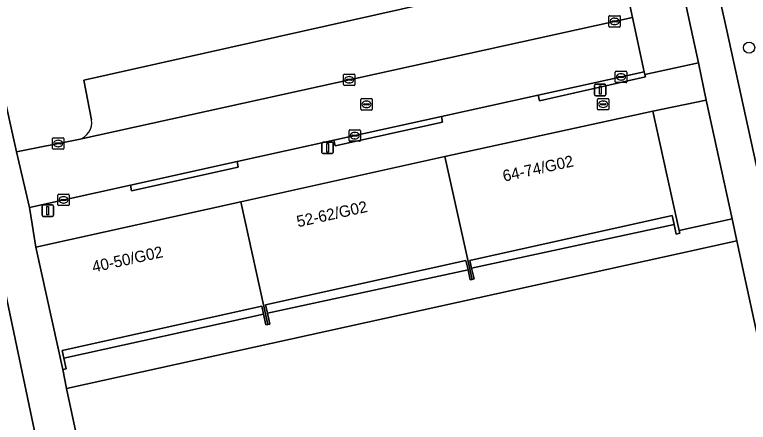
# Model space of a CAD drawing. Extents: x 160030 to 160839, y 385325 to 386450.
# Drawn here: x 160686.5 to 160750.9, y 385671.3 to 385707.1 of the extents above; entities that cross this region are included whole.
import ezdxf

# ---------------------------------------------------------------- set-up
doc = ezdxf.new("R2010")
doc.units = 0
for name, color, linetype in [('IMGEO_Berm_groen', 7, 'Continuous'), ('IMGEO_Boom', 7, 'Continuous'), ('IMGEO_Brandkraan', 7, 'Continuous'), ('IMGEO_Groenvoorziening', 7, 'Continuous'), ('IMGEO_Kolk', 7, 'Continuous'), ('IMGEO_Lichtmast', 7, 'Continuous'), ('IMGEO_Pand', 7, 'Continuous'), ('IMGEO_Pand_nummerreeks', 7, 'Continuous'), ('IMGEO_Parkeervlak_open', 7, 'Continuous'), ('IMGEO_Rijbaan_lokaal_open', 7, 'Continuous'), ('IMGEO_Rioolput', 7, 'Continuous'), ('IMGEO_Voetpad_open', 7, 'Continuous')]:
    doc.layers.add(name, color=color, linetype=linetype)

msp = doc.modelspace()

# ---------------------------------------------------------------- linework, layer by layer
at = {"layer": 'IMGEO_Berm_groen'}
msp.add_lwpolyline([(160752.149, 385706.509), (160750.95, 385712.317), (160750.418, 385714.749), (160747.106, 385714.042), (160747.585, 385711.838), (160748.912, 385705.94), (160756.742, 385670.124), (160764.406, 385634.512), (160767.671, 385635.207)], close=True, dxfattribs=at)
at = {"layer": 'IMGEO_Boom'}
msp.add_circle((160750.925, 385704.162), 0.489, dxfattribs=at)
at = {"layer": 'IMGEO_Brandkraan'}
for p, q in [((160737.616, 385698.769), (160737.616, 385699.621)), ((160737.691, 385699.695), (160738.543, 385699.695)), ((160738.104, 385699.475), (160738.129, 385699.475)), ((160738.617, 385699.621), (160738.617, 385698.769)), ((160737.875, 385699.189), (160737.875, 385699.201)), ((160738.313, 385699.152), (160737.915, 385699.152)), ((160737.918, 385699.238), (160738.316, 385699.238)), ((160738.127, 385698.915), (160738.102, 385698.915)), ((160738.359, 385699.201), (160738.359, 385699.189)), ((160738.543, 385698.695), (160737.691, 385698.695))]:
    msp.add_line(p, q, dxfattribs=at)
for points in [[(160737.616, 385698.769), (160737.616, 385699.621)], [(160737.691, 385699.695), (160738.543, 385699.695)], [(160738.617, 385699.621), (160738.617, 385698.769)], [(160738.543, 385698.695), (160737.691, 385698.695)]]:
    msp.add_lwpolyline(points, dxfattribs=at)
for centre, radius, start, end in [((160737.693, 385699.619), 0.0765, 91.55205, 178.44795), ((160737.693, 385699.619), 0.0765, 91.55205, 178.44795), ((160738.541, 385699.619), 0.0765, 1.55205, 88.44795), ((160738.541, 385699.619), 0.0765, 1.55205, 88.44795), ((160737.915, 385699.198), 0.0403, 85.87752, 175.75265), ((160737.912, 385699.188), 0.0366, 178.93798, 274.71019), ((160738.316, 385699.195), 0.043, 264.86636, 352.45326), ((160738.32, 385699.2), 0.0386, 1.73085, 96.63898), ((160737.693, 385698.771), 0.0765, 181.55205, 268.44795), ((160737.693, 385698.771), 0.0765, 181.55205, 268.44795), ((160738.541, 385698.771), 0.0765, 271.55205, 358.44795), ((160738.541, 385698.771), 0.0765, 271.55205, 358.44795)]:
    msp.add_arc(centre, radius, start, end, dxfattribs=at)
for centre, major_axis, ratio, start_param, end_param in [((160738.103, 385699.195), (-0.387, 0.002), 0.722429, 4.712389, 7.853982), ((160738.128, 385699.195), (-0.39, 0.002), 0.717154, 1.570796, 4.712389)]:
    msp.add_ellipse(centre, major_axis=major_axis, ratio=ratio, start_param=start_param, end_param=end_param, dxfattribs=at)
at = {"layer": 'IMGEO_Groenvoorziening'}
for points in [[(160692.533, 385701.29), (160739.614, 385711.868), (160740.697, 385706.808), (160741.718, 385702.039), (160741.772, 385701.797), (160746.478, 385702.821), (160741.383, 385726.239), (160736.6, 385725.195), (160682.511, 385713.385), (160686.606, 385695.006), (160692.066, 385696.105)], [(160693.191, 385697.833), (160692.533, 385701.29)], [(160704.845, 385661.028), (160724.924, 385665.504), (160748.512, 385670.542), (160749.509, 385665.757), (160750.548, 385660.927), (160750.648, 385660.947), (160750.687, 385660.776), (160755.372, 385661.736), (160750.486, 385684.225), (160749.841, 385687.196), (160745.072, 385686.16), (160691.006, 385674.252), (160695.339, 385654.015), (160697.696, 385654.461), (160698.29, 385654.583), (160703.979, 385655.723)]]:
    msp.add_lwpolyline(points, dxfattribs=at)
msp.add_lwpolyline([(160747.158, 385699.556), (160742.472, 385698.58), (160743.709, 385692.988), (160744.787, 385688.115), (160749.423, 385689.121)], close=True, dxfattribs=at)
msp.add_arc((160691.732, 385697.553), 1.486, 282.99435, 10.87404, dxfattribs=at)
at = {"layer": 'IMGEO_Kolk'}
for p, q in [((160738.618, 385706.036), (160738.618, 385706.888)), ((160738.693, 385706.962), (160739.545, 385706.962)), ((160739.106, 385706.742), (160739.131, 385706.742)), ((160739.619, 385706.888), (160739.619, 385706.036)), ((160739.545, 385705.962), (160738.693, 385705.962)), ((160738.877, 385706.456), (160738.877, 385706.468)), ((160739.315, 385706.419), (160738.917, 385706.419)), ((160738.92, 385706.505), (160739.318, 385706.505)), ((160739.129, 385706.182), (160739.104, 385706.182)), ((160739.361, 385706.468), (160739.361, 385706.456)), ((160739.253, 385702.091), (160740.105, 385702.091)), ((160715.325, 385700.91), (160715.325, 385701.762)), ((160715.4, 385701.836), (160716.252, 385701.836)), ((160715.813, 385701.616), (160715.838, 385701.616)), ((160716.326, 385701.762), (160716.326, 385700.91)), ((160739.178, 385701.165), (160739.178, 385702.017)), ((160739.437, 385701.585), (160739.437, 385701.597)), ((160739.875, 385701.548), (160739.477, 385701.548)), ((160739.48, 385701.634), (160739.878, 385701.634)), ((160739.666, 385701.871), (160739.691, 385701.871)), ((160739.921, 385701.597), (160739.921, 385701.585)), ((160740.179, 385702.017), (160740.179, 385701.165)), ((160716.252, 385700.836), (160715.4, 385700.836)), ((160715.584, 385701.33), (160715.584, 385701.342)), ((160716.022, 385701.293), (160715.624, 385701.293)), ((160715.627, 385701.379), (160716.025, 385701.379)), ((160715.836, 385701.056), (160715.811, 385701.056)), ((160716.068, 385701.342), (160716.068, 385701.33)), ((160740.105, 385701.091), (160739.253, 385701.091)), ((160739.689, 385701.311), (160739.664, 385701.311)), ((160715.883, 385696.938), (160716.735, 385696.938)), ((160689.857, 385696.247), (160690.709, 385696.247)), ((160715.808, 385696.012), (160715.808, 385696.864)), ((160716.067, 385696.432), (160716.067, 385696.444)), ((160716.505, 385696.395), (160716.107, 385696.395)), ((160716.11, 385696.481), (160716.508, 385696.481)), ((160716.296, 385696.718), (160716.321, 385696.718)), ((160716.551, 385696.444), (160716.551, 385696.432)), ((160716.809, 385696.864), (160716.809, 385696.012)), ((160689.782, 385695.321), (160689.782, 385696.173)), ((160690.041, 385695.741), (160690.041, 385695.753)), ((160690.479, 385695.704), (160690.081, 385695.704)), ((160690.084, 385695.79), (160690.482, 385695.79)), ((160690.27, 385696.027), (160690.295, 385696.027)), ((160690.525, 385695.753), (160690.525, 385695.741)), ((160690.783, 385696.173), (160690.783, 385695.321)), ((160716.735, 385695.938), (160715.883, 385695.938)), ((160716.319, 385696.158), (160716.294, 385696.158)), ((160690.709, 385695.247), (160689.857, 385695.247)), ((160690.293, 385695.467), (160690.268, 385695.467)), ((160690.249, 385690.373), (160690.249, 385691.225)), ((160690.324, 385691.299), (160691.176, 385691.299)), ((160691.25, 385691.225), (160691.25, 385690.373)), ((160690.508, 385690.793), (160690.508, 385690.805)), ((160690.946, 385690.756), (160690.548, 385690.756)), ((160690.551, 385690.842), (160690.949, 385690.842)), ((160690.76, 385690.519), (160690.735, 385690.519)), ((160690.737, 385691.079), (160690.762, 385691.079)), ((160690.992, 385690.805), (160690.992, 385690.793)), ((160691.176, 385690.299), (160690.324, 385690.299))]:
    msp.add_line(p, q, dxfattribs=at)
for points in [[(160738.618, 385706.036), (160738.618, 385706.888)], [(160738.693, 385706.962), (160739.545, 385706.962)], [(160739.619, 385706.888), (160739.619, 385706.036)], [(160739.545, 385705.962), (160738.693, 385705.962)], [(160739.253, 385702.091), (160740.105, 385702.091)], [(160715.325, 385700.91), (160715.325, 385701.762)], [(160715.4, 385701.836), (160716.252, 385701.836)], [(160716.326, 385701.762), (160716.326, 385700.91)], [(160739.178, 385701.165), (160739.178, 385702.017)], [(160740.179, 385702.017), (160740.179, 385701.165)], [(160716.252, 385700.836), (160715.4, 385700.836)], [(160740.105, 385701.091), (160739.253, 385701.091)], [(160715.883, 385696.938), (160716.735, 385696.938)], [(160689.857, 385696.247), (160690.709, 385696.247)], [(160715.808, 385696.012), (160715.808, 385696.864)], [(160716.809, 385696.864), (160716.809, 385696.012)], [(160689.782, 385695.321), (160689.782, 385696.173)], [(160690.783, 385696.173), (160690.783, 385695.321)], [(160716.735, 385695.938), (160715.883, 385695.938)], [(160690.709, 385695.247), (160689.857, 385695.247)], [(160690.249, 385690.373), (160690.249, 385691.225)], [(160690.324, 385691.299), (160691.176, 385691.299)], [(160691.25, 385691.225), (160691.25, 385690.373)], [(160691.176, 385690.299), (160690.324, 385690.299)]]:
    msp.add_lwpolyline(points, dxfattribs=at)
for centre, radius, start, end in [((160738.695, 385706.886), 0.0765, 91.55205, 178.44795), ((160738.695, 385706.886), 0.0765, 91.55205, 178.44795), ((160739.543, 385706.886), 0.0765, 1.55205, 88.44795), ((160739.543, 385706.886), 0.0765, 1.55205, 88.44795), ((160738.695, 385706.038), 0.0765, 181.55205, 268.44795), ((160738.695, 385706.038), 0.0765, 181.55205, 268.44795), ((160738.917, 385706.465), 0.0403, 85.87752, 175.75265), ((160738.914, 385706.455), 0.0366, 178.93798, 274.71019), ((160739.318, 385706.462), 0.043, 264.86636, 352.45326), ((160739.322, 385706.467), 0.0386, 1.73085, 96.63898), ((160739.543, 385706.038), 0.0765, 271.55205, 358.44795), ((160739.543, 385706.038), 0.0765, 271.55205, 358.44795), ((160739.255, 385702.015), 0.0765, 91.55205, 178.44795), ((160739.255, 385702.015), 0.0765, 91.55205, 178.44795), ((160740.103, 385702.015), 0.0765, 1.55205, 88.44795), ((160740.103, 385702.015), 0.0765, 1.55205, 88.44795), ((160715.402, 385701.76), 0.0765, 91.55205, 178.44795), ((160715.402, 385701.76), 0.0765, 91.55205, 178.44795), ((160716.25, 385701.76), 0.0765, 1.55205, 88.44795), ((160716.25, 385701.76), 0.0765, 1.55205, 88.44795), ((160739.477, 385701.594), 0.0403, 85.87752, 175.75265), ((160739.474, 385701.584), 0.0366, 178.93798, 274.71019), ((160739.878, 385701.591), 0.043, 264.86636, 352.45326), ((160739.882, 385701.596), 0.0386, 1.73085, 96.63898), ((160715.402, 385700.912), 0.0765, 181.55205, 268.44795), ((160715.402, 385700.912), 0.0765, 181.55205, 268.44795), ((160715.624, 385701.339), 0.0403, 85.87752, 175.75265), ((160715.621, 385701.329), 0.0366, 178.93798, 274.71019), ((160716.025, 385701.336), 0.043, 264.86636, 352.45326), ((160716.029, 385701.341), 0.0386, 1.73085, 96.63898), ((160716.25, 385700.912), 0.0765, 271.55205, 358.44795), ((160716.25, 385700.912), 0.0765, 271.55205, 358.44795), ((160739.255, 385701.167), 0.0765, 181.55205, 268.44795), ((160739.255, 385701.167), 0.0765, 181.55205, 268.44795), ((160740.103, 385701.167), 0.0765, 271.55205, 358.44795), ((160740.103, 385701.167), 0.0765, 271.55205, 358.44795), ((160715.885, 385696.862), 0.0765, 91.55205, 178.44795), ((160715.885, 385696.862), 0.0765, 91.55205, 178.44795), ((160716.733, 385696.862), 0.0765, 1.55205, 88.44795), ((160716.733, 385696.862), 0.0765, 1.55205, 88.44795), ((160689.859, 385696.171), 0.0765, 91.55205, 178.44795), ((160689.859, 385696.171), 0.0765, 91.55205, 178.44795), ((160690.707, 385696.171), 0.0765, 1.55205, 88.44795), ((160690.707, 385696.171), 0.0765, 1.55205, 88.44795), ((160716.107, 385696.441), 0.0403, 85.87752, 175.75265), ((160716.104, 385696.431), 0.0366, 178.93798, 274.71019), ((160716.508, 385696.438), 0.043, 264.86636, 352.45326), ((160716.512, 385696.443), 0.0386, 1.73085, 96.63898), ((160690.081, 385695.75), 0.0403, 85.87752, 175.75265), ((160690.078, 385695.74), 0.0366, 178.93798, 274.71019), ((160690.482, 385695.747), 0.043, 264.86636, 352.45326), ((160690.486, 385695.752), 0.0386, 1.73085, 96.63898), ((160715.885, 385696.014), 0.0765, 181.55205, 268.44795), ((160715.885, 385696.014), 0.0765, 181.55205, 268.44795), ((160716.733, 385696.014), 0.0765, 271.55205, 358.44795), ((160716.733, 385696.014), 0.0765, 271.55205, 358.44795), ((160689.859, 385695.323), 0.0765, 181.55205, 268.44795), ((160689.859, 385695.323), 0.0765, 181.55205, 268.44795), ((160690.707, 385695.323), 0.0765, 271.55205, 358.44795), ((160690.707, 385695.323), 0.0765, 271.55205, 358.44795), ((160690.326, 385691.223), 0.0765, 91.55205, 178.44795), ((160690.326, 385691.223), 0.0765, 91.55205, 178.44795), ((160691.174, 385691.223), 0.0765, 1.55205, 88.44795), ((160691.174, 385691.223), 0.0765, 1.55205, 88.44795), ((160690.548, 385690.802), 0.0403, 85.87752, 175.75265), ((160690.545, 385690.792), 0.0366, 178.93798, 274.71019), ((160690.949, 385690.799), 0.043, 264.86636, 352.45326), ((160690.953, 385690.804), 0.0386, 1.73085, 96.63898), ((160690.326, 385690.375), 0.0765, 181.55205, 268.44795), ((160690.326, 385690.375), 0.0765, 181.55205, 268.44795), ((160691.174, 385690.375), 0.0765, 271.55205, 358.44795), ((160691.174, 385690.375), 0.0765, 271.55205, 358.44795)]:
    msp.add_arc(centre, radius, start, end, dxfattribs=at)
for centre, major_axis, ratio, start_param, end_param in [((160739.105, 385706.462), (-0.387, 0.002), 0.722429, 4.712389, 7.853982), ((160739.13, 385706.462), (-0.39, 0.002), 0.717154, 1.570796, 4.712389), ((160715.812, 385701.336), (-0.387, 0.002), 0.722429, 4.712389, 7.853982), ((160715.837, 385701.336), (-0.39, 0.002), 0.717154, 1.570796, 4.712389), ((160739.665, 385701.591), (-0.387, 0.002), 0.722429, 4.712389, 7.853982), ((160739.69, 385701.591), (-0.39, 0.002), 0.717154, 1.570796, 4.712389), ((160716.295, 385696.438), (-0.387, 0.002), 0.722429, 4.712389, 7.853982), ((160716.32, 385696.438), (-0.39, 0.002), 0.717154, 1.570796, 4.712389), ((160690.269, 385695.747), (-0.387, 0.002), 0.722429, 4.712389, 7.853982), ((160690.294, 385695.747), (-0.39, 0.002), 0.717154, 1.570796, 4.712389), ((160690.736, 385690.799), (-0.387, 0.002), 0.722429, 4.712389, 7.853982), ((160690.761, 385690.799), (-0.39, 0.002), 0.717154, 1.570796, 4.712389)]:
    msp.add_ellipse(centre, major_axis=major_axis, ratio=ratio, start_param=start_param, end_param=end_param, dxfattribs=at)
at = {"layer": 'IMGEO_Lichtmast'}
for p, q in [((160737.362, 385700.039), (160737.362, 385700.839)), ((160737.362, 385700.839), (160737.362, 385700.039)), ((160737.462, 385700.939), (160738.252, 385700.939)), ((160738.252, 385700.939), (160737.462, 385700.939)), ((160738.352, 385700.839), (160738.352, 385700.039)), ((160738.352, 385700.039), (160738.352, 385700.839)), ((160738.252, 385699.939), (160737.462, 385699.939)), ((160737.462, 385699.939), (160738.252, 385699.939)), ((160713.425, 385694.956), (160713.425, 385695.756)), ((160713.425, 385695.756), (160713.425, 385694.956)), ((160713.525, 385695.856), (160714.315, 385695.856)), ((160714.315, 385695.856), (160713.525, 385695.856)), ((160714.415, 385695.756), (160714.415, 385694.956)), ((160714.415, 385694.956), (160714.415, 385695.756)), ((160714.315, 385694.856), (160713.525, 385694.856)), ((160713.525, 385694.856), (160714.315, 385694.856)), ((160688.868, 385689.451), (160688.868, 385690.251)), ((160688.868, 385690.251), (160688.868, 385689.451)), ((160688.968, 385690.351), (160689.758, 385690.351)), ((160689.758, 385690.351), (160688.968, 385690.351)), ((160689.858, 385690.251), (160689.858, 385689.451)), ((160689.858, 385689.451), (160689.858, 385690.251)), ((160689.758, 385689.351), (160688.968, 385689.351)), ((160688.968, 385689.351), (160689.758, 385689.351))]:
    msp.add_line(p, q, dxfattribs=at)
for points in [[(160737.782, 385700.814), (160737.932, 385700.814), (160737.932, 385700.064), (160737.782, 385700.064), (160737.782, 385700.814)], [(160713.845, 385695.731), (160713.995, 385695.731), (160713.995, 385694.981), (160713.845, 385694.981), (160713.845, 385695.731)], [(160689.288, 385690.226), (160689.438, 385690.226), (160689.438, 385689.476), (160689.288, 385689.476), (160689.288, 385690.226)]]:
    msp.add_lwpolyline(points, dxfattribs=at)
for centre, start, end in [((160737.462, 385700.839), 90, 180), ((160737.462, 385700.839), 90, 180), ((160738.252, 385700.839), 0, 90), ((160738.252, 385700.839), 360, 90), ((160737.462, 385700.039), 180, 270), ((160737.462, 385700.039), 180, 270), ((160738.252, 385700.039), 270, 0), ((160738.252, 385700.039), 270, 0), ((160713.525, 385695.756), 90, 180), ((160713.525, 385695.756), 90, 180), ((160714.315, 385695.756), 0, 90), ((160714.315, 385695.756), 360, 90), ((160713.525, 385694.956), 180, 270), ((160713.525, 385694.956), 180, 270), ((160714.315, 385694.956), 270, 0), ((160714.315, 385694.956), 270, 0), ((160688.968, 385690.251), 90, 180), ((160688.968, 385690.251), 90, 180), ((160689.758, 385690.251), 0, 90), ((160689.758, 385690.251), 360, 90), ((160688.968, 385689.451), 180, 270), ((160688.968, 385689.451), 180, 270), ((160689.758, 385689.451), 270, 0), ((160689.758, 385689.451), 270, 0)]:
    msp.add_arc(centre, 0.1, start, end, dxfattribs=at)
at = {"layer": 'IMGEO_Pand'}
for points in [[(160744.177, 385689.419), (160744.35, 385688.636), (160744.535, 385687.8), (160744.842, 385687.868), (160744.787, 385688.115), (160743.709, 385692.988), (160742.472, 385698.58), (160724.224, 385694.601), (160726.613, 385683.82), (160726.777, 385683.856), (160726.568, 385684.801), (160726.415, 385685.49)], [(160706.296, 385690.635), (160708.685, 385679.853), (160708.854, 385679.89), (160708.643, 385680.842), (160708.477, 385681.592), (160726.073, 385685.485), (160726.256, 385684.659), (160726.449, 385683.784), (160726.613, 385683.82), (160724.224, 385694.601)], [(160690.679, 385675.907), (160690.974, 385675.973), (160690.77, 385676.893), (160690.617, 385677.584), (160708.151, 385681.463), (160708.306, 385680.761), (160708.515, 385679.815), (160708.685, 385679.853), (160706.296, 385690.635), (160688.301, 385686.654)]]:
    msp.add_lwpolyline(points, close=True, dxfattribs=at)
at = {"layer": 'IMGEO_Parkeervlak_open'}
msp.add_lwpolyline([(160692.066, 385696.105), (160740.697, 385706.808), (160739.614, 385711.868), (160692.533, 385701.29), (160693.191, 385697.833)], dxfattribs=at)
msp.add_arc((160691.732, 385697.553), 1.486, 282.99435, 10.87404, dxfattribs=at)
at = {"layer": 'IMGEO_Rijbaan_lokaal_open'}
msp.add_lwpolyline([(160723.919, 385698.114), (160732.409, 385699.986), (160741.718, 385702.039), (160740.697, 385706.808), (160692.066, 385696.105), (160686.606, 385695.006), (160687.749, 385690.139), (160696.613, 385692.093), (160705.981, 385694.159), (160714.473, 385696.032)], close=True, dxfattribs=at)
msp.add_lwpolyline([(160689.852, 385662.934), (160689.287, 385665.363), (160685.918, 385681.39), (160684.387, 385688.526), (160682.93, 385695.313), (160682.595, 385696.638), (160680.996, 385703.498)], dxfattribs=at)
at = {"layer": 'IMGEO_Rioolput'}
for p, q in [((160716.845, 385698.756), (160716.845, 385699.608)), ((160716.92, 385699.682), (160717.772, 385699.682)), ((160717.333, 385699.462), (160717.358, 385699.462)), ((160717.846, 385699.608), (160717.846, 385698.756)), ((160717.104, 385699.176), (160717.104, 385699.188)), ((160717.542, 385699.139), (160717.144, 385699.139)), ((160717.147, 385699.225), (160717.545, 385699.225)), ((160717.356, 385698.902), (160717.331, 385698.902)), ((160717.588, 385699.188), (160717.588, 385699.176)), ((160717.772, 385698.682), (160716.92, 385698.682))]:
    msp.add_line(p, q, dxfattribs=at)
for points in [[(160716.845, 385698.756), (160716.845, 385699.608)], [(160716.92, 385699.682), (160717.772, 385699.682)], [(160717.846, 385699.608), (160717.846, 385698.756)], [(160717.772, 385698.682), (160716.92, 385698.682)]]:
    msp.add_lwpolyline(points, dxfattribs=at)
for centre, radius, start, end in [((160716.922, 385699.606), 0.0765, 91.55205, 178.44795), ((160716.922, 385699.606), 0.0765, 91.55205, 178.44795), ((160717.77, 385699.606), 0.0765, 1.55205, 88.44795), ((160717.77, 385699.606), 0.0765, 1.55205, 88.44795), ((160717.144, 385699.185), 0.0403, 85.87752, 175.75265), ((160717.141, 385699.175), 0.0366, 178.93798, 274.71019), ((160717.545, 385699.182), 0.043, 264.86636, 352.45326), ((160717.549, 385699.187), 0.0386, 1.73085, 96.63898), ((160716.922, 385698.758), 0.0765, 181.55205, 268.44795), ((160716.922, 385698.758), 0.0765, 181.55205, 268.44795), ((160717.77, 385698.758), 0.0765, 271.55205, 358.44795), ((160717.77, 385698.758), 0.0765, 271.55205, 358.44795)]:
    msp.add_arc(centre, radius, start, end, dxfattribs=at)
for centre, major_axis, ratio, start_param, end_param in [((160717.332, 385699.182), (-0.387, 0.002), 0.722429, 4.712389, 7.853982), ((160717.357, 385699.182), (-0.39, 0.002), 0.717154, 1.570796, 4.712389)]:
    msp.add_ellipse(centre, major_axis=major_axis, ratio=ratio, start_param=start_param, end_param=end_param, dxfattribs=at)
at = {"layer": 'IMGEO_Voetpad_open'}
for points in [[(160741.383, 385726.239), (160746.478, 385702.821), (160747.158, 385699.556), (160749.423, 385689.121), (160749.841, 385687.196), (160750.486, 385684.225), (160755.372, 385661.736), (160756.08, 385658.496), (160758.358, 385648.049), (160758.778, 385646.124), (160761.339, 385634.379), (160763.908, 385622.573), (160764.241, 385621.043), (160782.859, 385535.48), (160783.883, 385530.856), (160787.065, 385530.773), (160786.852, 385531.744), (160782.868, 385550.332), (160785.967, 385551.016), (160785.443, 385553.359), (160782.291, 385552.678), (160770.282, 385607.5)], [(160695.339, 385654.015), (160691.006, 385674.252), (160690.679, 385675.907), (160688.301, 385686.654), (160687.749, 385690.139), (160686.606, 385695.006), (160682.511, 385713.385)], [(160756.742, 385670.124), (160748.912, 385705.94), (160747.585, 385711.838)], [(160680.996, 385703.498), (160682.595, 385696.638), (160682.93, 385695.313), (160683.419, 385695.415), (160684.876, 385688.628), (160684.387, 385688.526), (160685.918, 385681.39), (160689.287, 385665.363), (160689.852, 385662.934)]]:
    msp.add_lwpolyline(points, dxfattribs=at)
for points in [[(160742.472, 385698.58), (160747.158, 385699.556), (160746.478, 385702.821), (160741.772, 385701.797), (160741.818, 385701.589), (160732.517, 385699.498), (160732.409, 385699.986), (160723.919, 385698.114), (160724.024, 385697.626), (160714.578, 385695.544), (160714.473, 385696.032), (160705.981, 385694.159), (160706.086, 385693.671), (160696.718, 385691.605), (160696.613, 385692.093), (160687.749, 385690.139), (160688.301, 385686.654), (160706.296, 385690.635), (160724.224, 385694.601)], [(160741.818, 385701.589), (160741.772, 385701.797), (160741.718, 385702.039), (160732.409, 385699.986), (160732.517, 385699.498)], [(160723.919, 385698.114), (160714.473, 385696.032), (160714.578, 385695.544), (160724.024, 385697.626)], [(160705.981, 385694.159), (160696.613, 385692.093), (160696.718, 385691.605), (160706.086, 385693.671)], [(160744.35, 385688.636), (160744.177, 385689.419), (160726.415, 385685.49), (160726.568, 385684.801)], [(160745.072, 385686.16), (160749.841, 385687.196), (160749.423, 385689.121), (160744.787, 385688.115), (160744.842, 385687.868), (160744.535, 385687.8), (160744.35, 385688.636), (160726.568, 385684.801), (160726.777, 385683.856), (160726.613, 385683.82), (160726.449, 385683.784), (160726.256, 385684.659), (160708.643, 385680.842), (160708.854, 385679.89), (160708.685, 385679.853), (160708.515, 385679.815), (160708.306, 385680.761), (160690.77, 385676.893), (160690.974, 385675.973), (160690.679, 385675.907), (160691.006, 385674.252)], [(160726.256, 385684.659), (160726.073, 385685.485), (160708.477, 385681.592), (160708.643, 385680.842)], [(160708.306, 385680.761), (160708.151, 385681.463), (160690.617, 385677.584), (160690.77, 385676.893)]]:
    msp.add_lwpolyline(points, close=True, dxfattribs=at)

# ---------------------------------------------------------------- texts
at = {"layer": 'IMGEO_Pand_nummerreeks'}
for s, p in [('64-74/G02', (160729.417, 385692.39)), ('52-62/G02', (160711.329, 385688.389)), ('40-50/G02', (160693.376, 385684.417))]:
    msp.add_text(s, height=1, rotation=12.47402, dxfattribs=at).set_placement(p)

doc.saveas('drawing.dxf')
